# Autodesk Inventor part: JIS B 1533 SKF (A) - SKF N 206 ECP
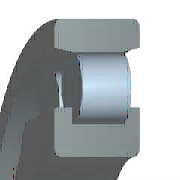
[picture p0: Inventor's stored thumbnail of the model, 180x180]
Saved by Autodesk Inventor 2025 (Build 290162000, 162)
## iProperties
Created: 2024-01
Part Number: JIS B 1533 SKF (A) - SKF N 206 ECP
Material: Acciaio, Dolce
Description: Cuscinetti a rulli cilindrici a fila singola tipo N SKF
Document SubType Name: Modeling
Standard: JIS B 1533 SKF
Designer: R5800u
Standard Revision: SKF 2013
Standards Organization: JIS
Language: it-IT
Size Designation: SKF N 206 ECP
Categories: <MemberInstance><Categories><Category DisplayName="Parti albero" InternalName="7f7aeb1f-a693-4053-b835-cee3144e0d98" Mnemonic="SHFT"><Category DisplayName="Cusc
Density: 7.85 g/cm^3
Appearance: Semilucidato
IsCustomPart: 0
Author: R5800u
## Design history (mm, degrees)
node "WorkPlane1"
node "WorkPoint1"
workplane "Work Plane2"
node "WorkPlane2"
node "WorkPoint2"
node "WorkAxis1"
pattern_circular "Seriepolare1" dims angle "d33" = 360 deg
body "Solid1"
node "Schizzo1"
extrude "Estrusione1" new body distance "d3" = 16 (= B); taper "d4" = 0 deg
node "Schizzo3"
sketch "Schizzo4"
  geometry: C1 r 31 at (0, 0) reference
hole "Foro1" sketch "Schizzo4" diameter "d6" = 30 (= Diam); stored, may be unused: countersink angle "d10" = 60 deg, drill point angle "d12" = 118 deg; dims "d7" = 6, "d8" = 4, "d9" = 2, "d11" = 8
revolve "Rivoluzione1" stored, may be unused: angle "d27" = 360 deg
revolve "Rivoluzione2" stored, may be unused: angle "d30" = 360 deg
node "Schizzo7"
fillet "Raccordo1" dims "d34" = 1 (= r)
node "Schizzo2" dims "d2" = 62 (= DD)
sketch "Schizzo5"
  geometry: L1 (20.6, 2.8)-(18.75, 2.8); L2 (20.6, 0)-(20.6, 2.8); L3 (28.244, 0)-(20.6, 0); L4 (27.75, 2.8)-(28.244, 0); L5 (27.75, 13.2)-(27.75, 2.8); L6 (28.244, 16)-(27.75, 13.2); L7 (20.6, 16)-(28.244, 16); L8 (20.6, 13.2)-(20.6, 16); L9 (18.75, 13.2)-(20.6, 13.2); L10 (18.75, 2.8)-(18.75, 13.2); L11 (-31, 0)-(31, 0) reference; L12 (-31, 16)-(31, 16) reference; L13 (0, 34.914)-(0, -22.914); L14 (0, -34.479)-(0, 46.479) reference; L15 (31, 0)-(31, 16) reference
  constraints: 22 end point, 4 collinear, 4 vertical, 3 horizontal, 2 horizontal alignment, 1 parallel, 1 vertical alignment
  dimensions: "d14" = 10.4 distance of L1.end L9.start (= msp_l0); "d16" = 2.8 distance of L8.start L7.start (= 0.5 x B - 0.5 x msp_l0); "d22" = 80 deg angle of L4 L3; "d36" = 41.2 diameter of L7.start L13 (= Diam1); "d37" = 9 distance between parallel lines of L5 L10 (= msp_dd0); "d38" = 55.5 diameter of L5.start L13 (= DD1)
sketch "Schizzo6"
  geometry: L1 (23.25, 2.8)-(23.25, 13.2); L2 (27.75, 2.8)-(23.25, 2.8); L3 (27.75, 13.2)-(27.75, 2.8); L4 (23.25, 13.2)-(27.75, 13.2); L5 (-27.75, 2.8)-(27.75, 2.8) reference; L6 (-20.6, 13.2)-(20.6, 13.2) reference; L7 (23.25, 2.8)-(23.25, 13.2); L8 (0, -2.4)-(0, 14.4) reference
  constraints: 10 end point, 2 collinear, 2 horizontal, 2 vertical
  dimensions: "d29" = 4.5 distance of L1.end L3.start (= 0.5 x msp_dd0); "d39" = 55.5 diameter of L3 L8 (= DD1)
other parameters: "Diam" = 30 [user parameter; used in 1 equation term], "DD" = 62 [user parameter; used in 1 equation term], "B" = 16 [user parameter; used in 4 equation terms], "r" = 1 [user parameter; used in 1 equation term], "Fw" = 37.5 [user parameter; used in 2 equation terms], "DD1" = 55.5 [user parameter; used in 4 equation terms], "Diam1" = 41.2 [user parameter; used in 1 equation term], "msp_dd0" = 9 (= -0.5 x Fw + 0.5 x DD1) [user parameter; used in 3 equation terms], "msp_mdtds" = 46.5 (= 0.5 x Fw + 0.5 x DD1) [user parameter; used in 1 equation term], "msp_l0" = 10.4 (= 0.65 x B) [user parameter; used in 2 equation terms], "d0" = -16 (computed from B), "d5" = 0, "d13" = 7.8 (derived), "d15" = 2.1 (derived), "d17" = 0 (derived), "d19" = 0 (derived), "d21" = 80 deg (derived), "d23" = 0 (derived), "d25" = 0 (derived), "d28" = 3.25 (derived), "d42" = 0, "d43" = 0, "d45" = 0, "d46" = 0, "d47" = 0
